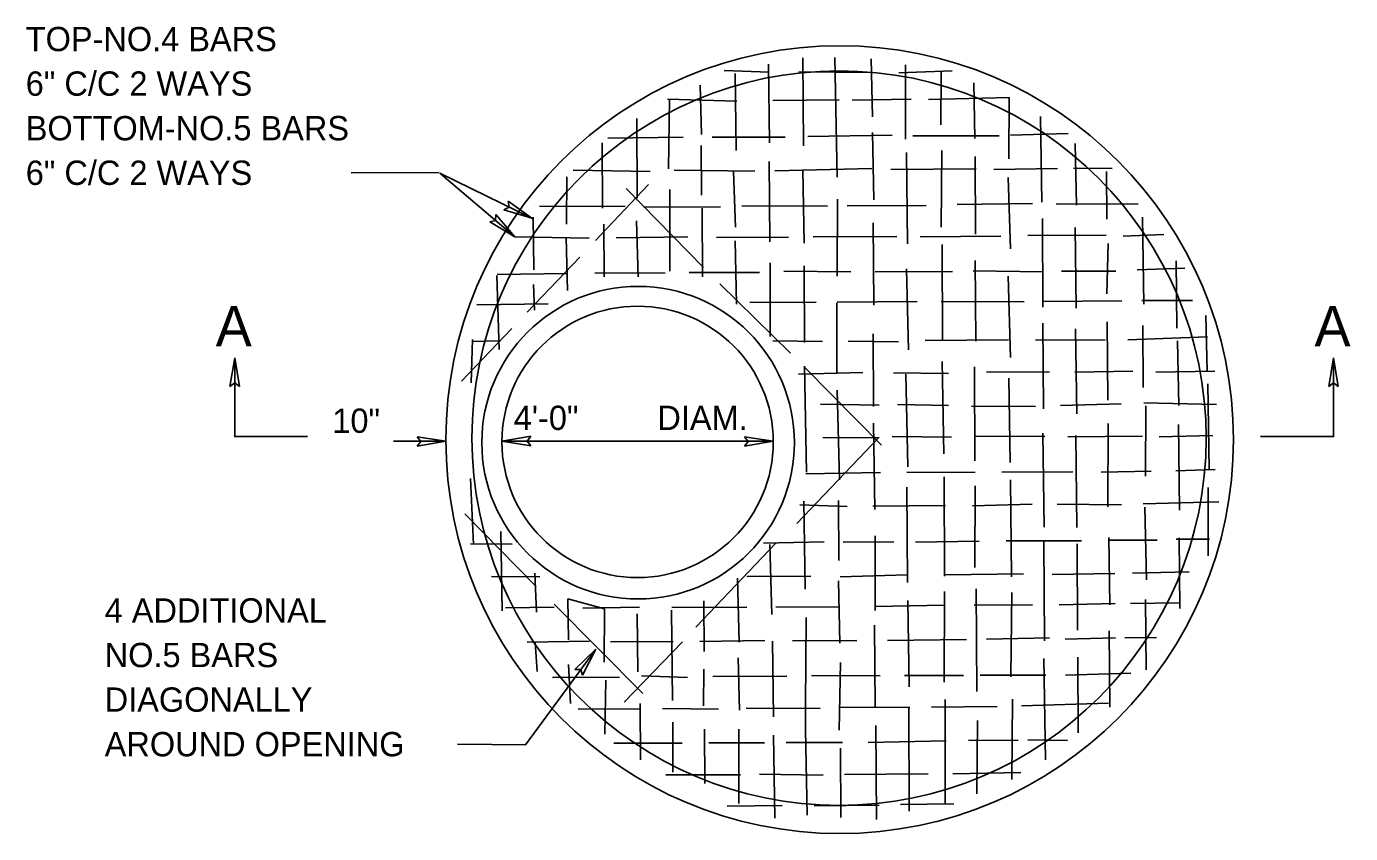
# Model space of a CAD drawing. Extents: x 8.6 to 15.9, y 6.4 to 16.6.
# Drawn here: x 11.915 to 15.183, y 14.645 to 16.636 of the extents above; entities that cross this region are included whole.
import ezdxf

# ---------------------------------------------------------------- set-up
doc = ezdxf.new("R2010")
doc.units = 0
for name, color, linetype in [('DETL-DIMS', 7, 'Continuous'), ('DETL-LINE', 7, 'Continuous'), ('DETL-NOTE', 7, 'Continuous')]:
    doc.layers.add(name, color=color, linetype=linetype)

msp = doc.modelspace()

# ---------------------------------------------------------------- linework, layer by layer
at = {"layer": 'DETL-DIMS'}
for p, q in [((12.7164, 16.2751), (12.9336, 16.2757)), ((12.9353, 16.2739), (13.1657, 16.1613)), ((13.1199, 16.1167), (12.9353, 16.2739)), ((13.0935, 16.1834), (13.1067, 16.1901)), ((13.0935, 16.1834), (13.1626, 16.1628)), ((13.1039, 16.2047), (13.1626, 16.1628)), ((13.1039, 16.2047), (13.1067, 16.1901)), ((13.0582, 16.1538), (13.0726, 16.157)), ((13.0582, 16.1538), (13.1199, 16.1167)), ((13.0736, 16.1718), (13.0726, 16.157)), ((13.0736, 16.1718), (13.1199, 16.1167)), ((12.417, 15.7477), (12.4289, 15.8188)), ((12.4408, 15.7477), (12.4289, 15.8188)), ((15.1291, 15.7477), (15.141, 15.8188)), ((15.1528, 15.7477), (15.141, 15.8188)), ((12.417, 15.7477), (12.4289, 15.7566)), ((12.4408, 15.7477), (12.4289, 15.7566)), ((15.1291, 15.7477), (15.141, 15.7566)), ((15.1528, 15.7477), (15.141, 15.7566)), ((12.879, 15.6238), (12.9502, 15.6125)), ((12.879, 15.6238), (12.888, 15.612)), ((13.1595, 15.625), (13.0885, 15.6125)), ((13.1595, 15.625), (13.1507, 15.6131)), ((13.6871, 15.6238), (13.7583, 15.6125)), ((13.6871, 15.6238), (13.6961, 15.612)), ((12.9502, 15.6125), (12.8206, 15.6125)), ((12.8792, 15.6001), (12.9502, 15.6125)), ((12.8792, 15.6001), (12.888, 15.612)), ((13.1597, 15.6013), (13.0885, 15.6125)), ((13.7583, 15.6125), (13.0885, 15.6125)), ((13.1597, 15.6013), (13.1507, 15.6131)), ((13.6873, 15.6001), (13.7583, 15.6125)), ((13.6873, 15.6001), (13.6961, 15.612)), ((13.3203, 15.0994), (13.1469, 14.8635)), ((13.2686, 15.0491), (13.3203, 15.0994)), ((13.2877, 15.0351), (13.3203, 15.0994)), ((13.2686, 15.0491), (13.2834, 15.0493)), ((13.2877, 15.0351), (13.2834, 15.0493)), ((13.1473, 14.8635), (12.9785, 14.8651))]:
    msp.add_line(p, q, dxfattribs=at)
for points in [[(12.6088, 15.6241), (12.4289, 15.6241), (12.4289, 15.8188)], [(14.961, 15.6241), (15.141, 15.6241), (15.141, 15.8188)]]:
    msp.add_lwpolyline(points, dxfattribs=at)
at = {"layer": 'DETL-LINE'}
for p, q in [((13.746, 16.5429), (13.7486, 16.3488)), ((13.8332, 16.3414), (13.8313, 16.559)), ((13.9162, 16.2639), (13.9098, 16.5591)), ((14.0002, 16.5565), (14.0032, 16.4129)), ((14.0846, 16.3576), (14.0842, 16.5411)), ((13.748, 16.523), (13.6368, 16.5271)), ((13.6664, 16.3296), (13.6642, 16.5198)), ((14.0034, 16.5228), (13.8216, 16.5245)), ((14.1998, 16.5263), (14.0685, 16.5213)), ((14.1715, 16.3931), (14.1727, 16.5243)), ((13.5775, 16.4913), (13.5812, 16.3694)), ((14.2531, 16.497), (14.2558, 16.36)), ((13.4974, 16.4566), (13.6685, 16.4519)), ((13.4993, 16.2846), (13.5023, 16.4574)), ((13.7567, 16.4533), (13.9212, 16.4549)), ((13.9526, 16.4541), (14.0989, 16.4568)), ((14.1415, 16.4559), (14.3414, 16.4611)), ((14.3399, 16.3091), (14.3401, 16.4598)), ((13.4219, 16.2127), (13.4212, 16.409)), ((14.4176, 16.4135), (14.4214, 16.2025)), ((14.0033, 16.3743), (14.0061, 16.2085)), ((13.3359, 16.3491), (13.337, 16.1878)), ((13.5355, 16.3632), (13.3502, 16.3605)), ((13.5801, 16.342), (13.5811, 16.2201)), ((13.7877, 16.3626), (13.6073, 16.363)), ((14.052, 16.3681), (13.8436, 16.3647)), ((14.3161, 16.3661), (14.1025, 16.3663)), ((14.4864, 16.3716), (14.3441, 16.3681)), ((14.5069, 16.195), (14.5035, 16.3471)), ((14.0893, 16.1001), (14.087, 16.3253)), ((14.1725, 16.141), (14.1744, 16.3298)), ((14.2567, 16.3148), (14.257, 16.1234)), ((13.2639, 16.2811), (13.4545, 16.278)), ((13.5139, 16.2818), (13.7129, 16.2791)), ((13.6646, 16.1408), (13.6601, 16.2778)), ((13.7481, 16.3027), (13.7498, 16.1046)), ((13.7621, 16.28), (14.0015, 16.2853)), ((13.8344, 16.1011), (13.8313, 16.282)), ((14.048, 16.2831), (14.259, 16.2847)), ((14.3025, 16.2834), (14.4599, 16.2859)), ((14.4989, 16.286), (14.595, 16.2855)), ((14.5808, 16.2781), (14.5814, 16.1602)), ((13.2486, 16.2648), (13.248, 16.1483)), ((13.4506, 16.2457), (13.3194, 16.1077)), ((14.344, 16.0875), (14.3382, 16.2631)), ((13.586, 16.041), (13.3955, 16.236)), ((13.503, 16.032), (13.5028, 16.2336)), ((13.9156, 16.0197), (13.917, 16.2098)), ((13.3929, 16.1921), (13.181, 16.1923)), ((13.6278, 16.1908), (13.439, 16.1904)), ((13.583, 16.1881), (13.5836, 16.0184)), ((13.892, 16.1928), (13.681, 16.1938)), ((14.1358, 16.1945), (13.9403, 16.1937)), ((14.3983, 16.1996), (14.2121, 16.1964)), ((14.6585, 16.1981), (14.4568, 16.1977)), ((13.1657, 16.1654), (13.1671, 16.0355)), ((13.3402, 16.1483), (13.3411, 16.0184)), ((13.4245, 16.0181), (13.4209, 16.1564)), ((14.0051, 16.1518), (14.0062, 15.948)), ((14.4223, 16.1621), (14.4233, 15.9432)), ((14.6729, 15.9511), (14.6697, 16.1651)), ((13.1191, 16.1167), (13.3035, 16.1136)), ((13.2472, 16.1155), (13.2504, 15.9847)), ((13.3704, 16.1148), (13.5473, 16.1171)), ((13.6178, 16.1155), (13.796, 16.1161)), ((13.8563, 16.1169), (14.0628, 16.1176)), ((14.1205, 16.1171), (14.3199, 16.1188)), ((14.3869, 16.1199), (14.5797, 16.1208)), ((14.5057, 15.9407), (14.5036, 16.1401)), ((14.6222, 16.1186), (14.722, 16.123)), ((13.6672, 15.9507), (13.6638, 16.1067)), ((14.1756, 15.8635), (14.1748, 16.098)), ((14.5848, 16.1004), (14.5819, 15.9763)), ((13.2804, 16.0668), (13.1506, 15.9311)), ((13.7506, 16.0527), (13.7502, 15.871)), ((14.2569, 16.0587), (14.258, 15.8596)), ((14.7524, 16.058), (14.7543, 15.8918)), ((13.0819, 15.8391), (13.0761, 16.0213)), ((13.2495, 16.0268), (13.077, 16.0244)), ((13.491, 16.0277), (13.3177, 16.028)), ((13.7246, 16.0286), (13.5505, 16.0293)), ((13.9499, 16.0309), (13.7845, 16.032)), ((13.8351, 15.856), (13.8348, 16.0453)), ((14.2003, 16.0313), (14.0101, 16.0304)), ((14.092, 15.8381), (14.0869, 16.0376)), ((14.4246, 16.0309), (14.2513, 16.0334)), ((14.3441, 15.8194), (14.3376, 16.0202)), ((14.6037, 16.0324), (14.4698, 16.0323)), ((14.7744, 16.0396), (14.6565, 16.0354)), ((13.1663, 15.9992), (13.1692, 15.9358)), ((13.8008, 15.8298), (13.626, 16.0011)), ((13.2026, 15.9519), (13.0262, 15.9491)), ((13.7, 15.9553), (13.864, 15.9555)), ((13.9151, 15.7813), (13.9154, 15.9537)), ((13.9163, 15.9554), (14.1132, 15.9572)), ((14.1725, 15.9571), (14.3773, 15.9565)), ((14.4239, 15.9578), (14.6189, 15.9587)), ((14.6681, 15.9595), (14.7932, 15.9601)), ((14.8291, 15.7852), (14.8256, 15.9226)), ((13.1129, 15.8907), (12.9885, 15.7611)), ((14.4233, 15.9042), (14.4253, 15.6923)), ((14.5076, 15.68), (14.5043, 15.8901)), ((14.5821, 15.9076), (14.5838, 15.7139)), ((14.6709, 15.7454), (14.6706, 15.8979)), ((13.016, 15.8633), (13.0123, 15.7569)), ((13.0789, 15.86), (13.0142, 15.8588)), ((13.8795, 15.8587), (13.7572, 15.8603)), ((14.067, 15.8579), (13.9433, 15.8599)), ((14.0051, 15.878), (14.0056, 15.6984)), ((14.3388, 15.8629), (14.133, 15.8608)), ((14.5777, 15.8629), (14.4052, 15.8623)), ((14.8299, 15.8703), (14.6335, 15.8628)), ((14.7558, 15.8603), (14.7592, 15.7007)), ((13.84, 15.5365), (13.8355, 15.798)), ((14.025, 15.603), (13.8372, 15.794)), ((14.1791, 15.5816), (14.1751, 15.8094)), ((14.2548, 15.7963), (14.256, 15.5641)), ((14.5024, 15.7834), (14.646, 15.7851)), ((14.7023, 15.7828), (14.8478, 15.7854)), ((13.8202, 15.7777), (13.9789, 15.7825)), ((14.0552, 15.7813), (14.1903, 15.7796)), ((14.0901, 15.5492), (14.0853, 15.7784)), ((14.2843, 15.7827), (14.4399, 15.7839)), ((14.3429, 15.5601), (14.34, 15.7685)), ((14.8343, 15.5418), (14.831, 15.7546)), ((13.9214, 15.5171), (13.916, 15.7387)), ((14.0193, 15.7019), (13.8749, 15.7037)), ((14.1909, 15.7007), (14.065, 15.7032)), ((14.4054, 15.6983), (14.2472, 15.6988)), ((14.6165, 15.7052), (14.4675, 15.7004)), ((14.8518, 15.7034), (14.6732, 15.7077)), ((14.6768, 15.526), (14.6776, 15.7002)), ((14.0056, 15.6573), (14.0089, 15.444)), ((14.5845, 15.6567), (14.5843, 15.4511)), ((13.8162, 15.4095), (14.0199, 15.623)), ((13.8807, 15.6221), (14.0163, 15.6213)), ((14.0514, 15.624), (14.1977, 15.6227)), ((14.2571, 15.6248), (14.4286, 15.624)), ((14.4238, 15.6321), (14.4269, 15.4003)), ((14.4849, 15.6235), (14.6698, 15.6253)), ((14.5076, 15.3995), (14.5053, 15.6264)), ((14.711, 15.6232), (14.8435, 15.6264)), ((14.7583, 15.6538), (14.7611, 15.4423)), ((14.0226, 15.5352), (13.8386, 15.532)), ((14.2567, 15.5357), (14.0878, 15.5359)), ((14.181, 15.2798), (14.1799, 15.5249)), ((14.4978, 15.537), (14.3223, 15.536)), ((14.6906, 15.5387), (14.5679, 15.5359)), ((14.8489, 15.5426), (14.7518, 15.5395)), ((13.0105, 15.5203), (13.0182, 15.3575)), ((14.0896, 15.2642), (14.0879, 15.4991)), ((14.2568, 15.5029), (14.2553, 15.3008)), ((14.3464, 15.2783), (14.3434, 15.5171)), ((14.8314, 15.3295), (14.8317, 15.4984)), ((13.8368, 15.2475), (13.834, 15.4647)), ((13.9199, 15.3185), (13.9191, 15.4661)), ((14.6708, 15.4578), (14.8579, 15.4627)), ((12.9968, 15.4331), (13.1724, 15.2551)), ((13.8237, 15.4555), (13.9407, 15.4513)), ((14.0036, 15.4521), (14.1832, 15.4539)), ((14.2497, 15.4533), (14.3973, 15.4573)), ((14.4585, 15.4571), (14.618, 15.4557)), ((14.6792, 15.2703), (14.6756, 15.4498)), ((13.0889, 15.1938), (13.0859, 15.3901)), ((13.5668, 15.1534), (13.7634, 15.3599)), ((13.884, 15.3641), (13.7342, 15.3611)), ((14.0555, 15.3647), (13.931, 15.3632)), ((14.0096, 15.3793), (14.01, 15.195)), ((14.2666, 15.3658), (14.1096, 15.3638)), ((14.5192, 15.3666), (14.333, 15.3665)), ((14.4261, 15.3644), (14.4273, 15.1197)), ((14.5862, 15.3748), (14.589, 15.2086)), ((14.7059, 15.3684), (14.5888, 15.3686)), ((14.8353, 15.3707), (14.7529, 15.3706)), ((14.7604, 15.3745), (14.7619, 15.1999)), ((13.0107, 15.3598), (13.1135, 15.3589)), ((13.7496, 15.3574), (13.755, 15.1849)), ((14.5091, 15.1464), (14.5085, 15.3592)), ((13.0627, 15.2787), (13.1819, 15.2784)), ((13.17, 15.2874), (13.1735, 15.1912)), ((13.6737, 15.117), (13.6695, 15.2748)), ((13.693, 15.279), (13.8513, 15.2797)), ((13.9228, 15.1142), (13.919, 15.268)), ((13.9235, 15.2782), (14.0885, 15.2828)), ((14.182, 15.2833), (14.3762, 15.2855)), ((14.4462, 15.2835), (14.6009, 15.2861)), ((14.6448, 15.2874), (14.7849, 15.2901)), ((14.1799, 15.0179), (14.1807, 15.2421)), ((14.2588, 15.248), (14.2603, 14.9954)), ((14.3449, 15.031), (14.3469, 15.2392)), ((13.2171, 15.2028), (13.0974, 15.2013)), ((13.2172, 15.2103), (13.4362, 14.9898)), ((13.2526, 15.1223), (13.2514, 15.2237)), ((13.2514, 15.2237), (13.3416, 15.199)), ((13.4276, 15.203), (13.288, 15.2008)), ((13.3416, 15.199), (13.3408, 15.0678)), ((13.6927, 15.2028), (13.5079, 15.2027)), ((13.5865, 15.2188), (13.5879, 15.0938)), ((13.9219, 15.2028), (13.7645, 15.2039)), ((14.1808, 15.2084), (14.0101, 15.2051)), ((14.0933, 15.0067), (14.0905, 15.2195)), ((14.398, 15.2091), (14.2544, 15.2082)), ((14.6019, 15.212), (14.464, 15.2093)), ((14.7629, 15.2136), (14.6401, 15.2126)), ((14.6784, 15.0487), (14.677, 15.2224)), ((13.4239, 15.0435), (13.4222, 15.1871)), ((13.5069, 15.1957), (13.5092, 14.9731)), ((13.838, 14.9603), (13.8396, 15.1775)), ((14.0083, 15.1586), (14.0099, 14.9561)), ((14.5871, 15.1444), (14.5893, 14.956)), ((13.1506, 15.117), (13.3045, 15.1191)), ((13.1702, 15.1168), (13.1752, 15.0445)), ((13.3563, 15.1177), (13.511, 15.1185)), ((13.3903, 14.9685), (13.5341, 15.1178)), ((13.5771, 15.1183), (13.7371, 15.1208)), ((13.7566, 15.1189), (13.7588, 14.9327)), ((13.8054, 15.1202), (13.9641, 15.1205)), ((14.0399, 15.1207), (14.2349, 15.1233)), ((14.2842, 15.1241), (14.4398, 15.1271)), ((14.4783, 15.1245), (14.6029, 15.1274)), ((14.6259, 15.1272), (14.7044, 15.1282)), ((13.6748, 14.949), (13.6716, 15.0784)), ((13.9212, 14.8997), (13.9241, 15.0663)), ((14.426, 15.0763), (14.4302, 14.8263)), ((14.5111, 14.8929), (14.5098, 15.0795)), ((13.2578, 14.9653), (13.253, 15.0615)), ((13.5461, 15.03), (13.4326, 15.0333)), ((13.5871, 15.05), (13.5858, 14.9596)), ((14.0218, 15.034), (13.8529, 15.0342)), ((14.2279, 15.0343), (14.0825, 15.0347)), ((14.4313, 15.0355), (14.2687, 15.0357)), ((14.6411, 15.0406), (14.4792, 15.0355)), ((13.379, 15.0307), (13.2136, 15.0295)), ((13.3448, 15.0234), (13.3426, 14.8896)), ((13.7917, 15.033), (13.6086, 15.0321)), ((14.1827, 14.716), (14.1821, 14.9753)), ((14.3469, 14.7779), (14.3488, 14.976)), ((13.2763, 14.9518), (13.431, 14.9526)), ((13.4302, 14.8267), (13.4298, 14.9655)), ((13.4846, 14.953), (13.6229, 14.9517)), ((13.6916, 14.9537), (13.8738, 14.9534)), ((13.8374, 14.9014), (13.838, 14.9603)), ((13.9244, 14.956), (14.0955, 14.9553)), ((14.0939, 14.6996), (14.0928, 14.9548)), ((14.1487, 14.9561), (14.3105, 14.9577)), ((14.3708, 14.9594), (14.5854, 14.9662)), ((13.51, 14.9191), (13.5106, 14.7963)), ((13.6734, 14.719), (13.673, 14.9025)), ((14.0117, 14.9113), (14.013, 14.6791)), ((14.2623, 14.9231), (14.261, 14.7428)), ((13.5883, 14.902), (13.5892, 14.7681)), ((13.7584, 14.8871), (13.7617, 14.6823)), ((13.8416, 14.6895), (13.8374, 14.9014)), ((14.1846, 14.8733), (13.9922, 14.8694)), ((14.3629, 14.8743), (14.2401, 14.8746)), ((14.4843, 14.8745), (14.3863, 14.8754)), ((13.5335, 14.8674), (13.365, 14.8677)), ((13.7369, 14.8687), (13.5995, 14.8681)), ((13.9293, 14.8695), (13.7897, 14.8695)), ((13.9253, 14.6843), (13.9243, 14.8554)), ((13.4928, 14.7898), (13.6772, 14.7894)), ((13.7242, 14.7908), (13.8815, 14.7888)), ((13.9343, 14.7901), (14.1409, 14.7922)), ((14.2016, 14.7916), (14.3692, 14.795)), ((13.6441, 14.7122), (13.7798, 14.714)), ((13.8595, 14.7128), (14.0196, 14.7144)), ((14.0719, 14.7162), (14.2035, 14.7181))]:
    msp.add_line(p, q, dxfattribs=at)
for centre, radius in [((13.9221, 15.6166), 0.972), ((13.9206, 15.6203), 0.9062), ((13.4245, 15.609), 0.3857), ((13.4234, 15.611), 0.3349)]:
    msp.add_circle(centre, radius, dxfattribs=at)

# ---------------------------------------------------------------- texts
at = {"layer": 'DETL-NOTE'}
for s, height, p in [('TOP-NO.4 BARS', 0.06, (11.9131, 16.5751)), ('6" C/C 2 WAYS', 0.06, (11.9131, 16.4651)), ('BOTTOM-NO.5 BARS', 0.06, (11.9131, 16.3551)), ('6" C/C 2 WAYS', 0.06, (11.9131, 16.2451)), ('A', 0.1, (12.3819, 15.8466)), ('A', 0.1, (15.094, 15.8466)), ('10"', 0.06, (12.6699, 15.6333)), ('4\'-0"', 0.06, (13.1176, 15.6403)), ('DIAM.', 0.06, (13.4721, 15.6403)), ('4 ADDITIONAL', 0.06, (12.108, 15.1651)), ('NO.5 BARS', 0.06, (12.108, 15.0551)), ('DIAGONALLY', 0.06, (12.108, 14.9451)), ('AROUND OPENING', 0.06, (12.108, 14.8351))]:
    msp.add_text(s, height=height, dxfattribs=at).set_placement(p)

doc.saveas('drawing.dxf')
